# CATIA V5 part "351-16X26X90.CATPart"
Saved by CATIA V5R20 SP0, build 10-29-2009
Part number: 351-16X26X90
Definition: NONE
Nomenclature: 351-16X26X90
Source: Unknown
Description: 351-16X26X90
Bounding box of the stored display mesh (mm): x -5 to 85, y -13 to 13, z -13 to 13
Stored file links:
  C:\Users\Utente\Desktop\IO LAVORO\3D X SITO CF\X SITO\PLASTICA\351\351-16X26X90.CATPart
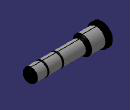
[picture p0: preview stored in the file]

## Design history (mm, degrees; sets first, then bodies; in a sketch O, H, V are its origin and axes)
Body1 "351-16X26X90" (main body)
  Solid1: solid without history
